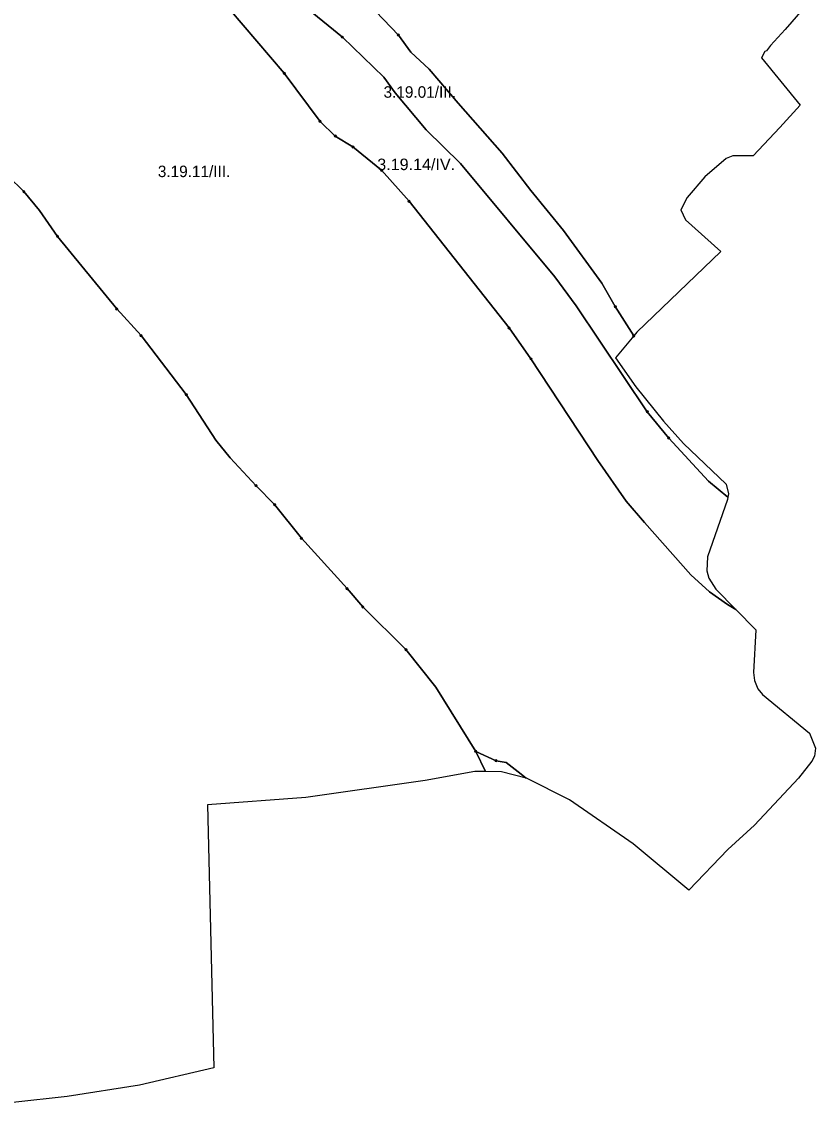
# Model space of a CAD drawing. Extents: x -650455 to -642254, y -1075222 to -1066610.
# Drawn here: x -644416 to -643724, y -1073642 to -1072701 of the extents above; entities that cross this region are included whole.
import ezdxf
from ezdxf.enums import TextEntityAlignment as Align

# ---------------------------------------------------------------- set-up
doc = ezdxf.new("R2010")
doc.units = 0
doc.header["$LTSCALE"] = 4
doc.header["$PDMODE"] = 32
doc.header["$PDSIZE"] = 2
for name, color, linetype, lineweight in [('1', 7, 'Continuous', 25), ('11', 7, 'Continuous', 13), ('12', 7, 'Continuous', 13), ('13', 7, 'Continuous', 13), ('14', 7, 'Continuous', 13)]:
    doc.layers.add(name, color=color, linetype=linetype, lineweight=lineweight)
doc.layers.add('2', color=7, linetype='Continuous')

msp = doc.modelspace()

# ---------------------------------------------------------------- linework, layer by layer
at = {"layer": '1'}
for points in [[(-644133.59, -1072663.941), (-644087.515, -1072712.377), (-644076.499, -1072727.239), (-644060.762, -1072741.927), (-644035.408, -1072771.653), (-643997.027, -1072815.367), (-643971.935, -1072847.715), (-643943.434, -1072882.512), (-643910.123, -1072928.499), (-643898.495, -1072948.957)], [(-643734.991, -1072689.776), (-643750.231, -1072707.416), (-643763.214, -1072721.526), (-643766.742, -1072726.043), (-643768.011, -1072726.748), (-643770.864, -1072732.304), (-643737.297, -1072773.436), (-643755.036, -1072793.028), (-643778.183, -1072817.707), (-643795.921, -1072817.707), (-643801.762, -1072819.98), (-643820.366, -1072835.782), (-643835.725, -1072853.968), (-643841.349, -1072864.684), (-643837.239, -1072873.344), (-643806.535, -1072901.023), (-643879.504, -1072971.156), (-643882.299, -1072974.5), (-643898.495, -1072948.957), (-643910.123, -1072928.499), (-643943.434, -1072882.512), (-643971.935, -1072847.715), (-643997.027, -1072815.367), (-644035.408, -1072771.653), (-644060.762, -1072741.927), (-644076.499, -1072727.239), (-644087.515, -1072712.377), (-644133.59, -1072663.941)], [(-644234.796, -1072689.872), (-644186.973, -1072745.651), (-644155.761, -1072787.617), (-644142.471, -1072800.381), (-644127.172, -1072809.824), (-644102.167, -1072830.107), (-644078.124, -1072857.21), (-643990.959, -1072967.544), (-643971.987, -1072994.472), (-643913.497, -1073082.949), (-643888.93, -1073118.445), (-643872.93, -1073137.155), (-643832.539, -1073182.792), (-643816.189, -1073197.48), (-643800.627, -1073208.496), (-643793.212, -1073213.013), (-643775.773, -1073230.523), (-643778.031, -1073267.918), (-643777.184, -1073274.69), (-643774.079, -1073282.028), (-643769.987, -1073286.968), (-643729.064, -1073320.694)], [(-644165.902, -1072690.047), (-644136.264, -1072714.177), (-644100.069, -1072749.148), (-644090.364, -1072762.787), (-644063.262, -1072794.961), (-644033.274, -1072824.162), (-643951.179, -1072922.956), (-643932.382, -1072948.31), (-643870.57, -1073040.634), (-643851.773, -1073063.54), (-643817.151, -1073100.96), (-643800.254, -1073115.142), (-643800.608, -1073117.208), (-643818.106, -1073166.881), (-643818.53, -1073179.298), (-643816.837, -1073185.507), (-643810.91, -1073195.243), (-643793.212, -1073213.013), (-643800.627, -1073208.496), (-643816.189, -1073197.48), (-643832.539, -1073182.792), (-643872.93, -1073137.155), (-643888.93, -1073118.445), (-643913.497, -1073082.949), (-643971.987, -1072994.472), (-643990.959, -1072967.544), (-644078.124, -1072857.21), (-644102.167, -1072830.107), (-644127.172, -1072809.824), (-644142.471, -1072800.381), (-644155.761, -1072787.617), (-644186.973, -1072745.651), (-644234.796, -1072689.872)], [(-643799.762, -1073112.269), (-643800.254, -1073115.142), (-643817.151, -1073100.96), (-643851.773, -1073063.54), (-643870.57, -1073040.634), (-643932.382, -1072948.31), (-643951.179, -1072922.956), (-644033.274, -1072824.162), (-644063.262, -1072794.961), (-644090.364, -1072762.787), (-644100.069, -1072749.148), (-644136.264, -1072714.177), (-644165.902, -1072690.047)], [(-644427.764, -1072835.165), (-644413.997, -1072848.687), (-644400.183, -1072865.124), (-644384.621, -1072887.855), (-644332.951, -1072950.978), (-644311.793, -1072974.234), (-644272.363, -1073025.642), (-644246.747, -1073065.334), (-644234.157, -1073080.721), (-644211.513, -1073105.026), (-644195.427, -1073121.463), (-644172.083, -1073150.839), (-644132.216, -1073194.728), (-644118.49, -1073210.64), (-644080.896, -1073247.884), (-644054.929, -1073280.582), (-644020.045, -1073336.536), (-644011.677, -1073354.192), (-644020.886, -1073354.137), (-644064.067, -1073362.039), (-644168.209, -1073376.856), (-644253.864, -1073383.206), (-644248.437, -1073612.322), (-644313.273, -1073627.474), (-644376.209, -1073637.35), (-644423.623, -1073642.431)], [(-643729.064, -1073320.694), (-643723.984, -1073333.675), (-643724.69, -1073340.59), (-643726.947, -1073344.965), (-643738.66, -1073359.782), (-643777.043, -1073400.846), (-643800.326, -1073422.013), (-643834.173, -1073457.614), (-643882.878, -1073417.215), (-643938.194, -1073378.691), (-643975.73, -1073359.923), (-643976.242, -1073359.79), (-643983.062, -1073354.416), (-643993.414, -1073346.315), (-644002.385, -1073344.755), (-644020.045, -1073336.536), (-644054.929, -1073280.582), (-644080.896, -1073247.884), (-644118.49, -1073210.64), (-644132.216, -1073194.728), (-644172.083, -1073150.839), (-644195.427, -1073121.463), (-644211.513, -1073105.026), (-644234.157, -1073080.721), (-644246.747, -1073065.334), (-644272.363, -1073025.642), (-644311.793, -1072974.234), (-644332.951, -1072950.978), (-644384.621, -1072887.855), (-644400.183, -1072865.124), (-644413.997, -1072848.687), (-644427.764, -1072835.165)], [(-643898.495, -1072948.957), (-643882.299, -1072974.5), (-643898.324, -1072993.671), (-643880.62, -1073018.853), (-643856.489, -1073048.91), (-643838.991, -1073068.243), (-643801.737, -1073103.803), (-643799.762, -1073112.269)]]:
    msp.add_lwpolyline(points, dxfattribs=at)
msp.add_lwpolyline([(-643983.062, -1073354.416), (-643976.242, -1073359.79), (-643997.462, -1073354.278), (-644011.677, -1073354.192), (-644020.045, -1073336.536), (-644002.385, -1073344.755), (-643993.414, -1073346.315)], close=True, dxfattribs=at)
at = {"layer": '11'}
for points in [[(-644133.59, -1072663.941), (-644087.515, -1072712.377), (-644076.499, -1072727.239), (-644060.762, -1072741.927), (-644035.408, -1072771.653)], [(-643882.299, -1072974.5), (-643879.504, -1072971.156), (-643806.535, -1072901.023), (-643837.239, -1072873.344), (-643841.349, -1072864.684), (-643835.725, -1072853.968), (-643820.366, -1072835.782), (-643801.762, -1072819.98), (-643795.921, -1072817.707), (-643778.183, -1072817.707), (-643755.036, -1072793.028), (-643737.297, -1072773.436), (-643770.864, -1072732.304), (-643768.011, -1072726.748), (-643766.742, -1072726.043), (-643763.214, -1072721.526), (-643750.231, -1072707.416), (-643734.991, -1072689.776)], [(-644035.408, -1072771.653), (-643997.027, -1072815.367), (-643971.935, -1072847.715), (-643943.434, -1072882.512), (-643910.123, -1072928.499), (-643898.495, -1072948.957), (-643882.299, -1072974.5)]]:
    msp.add_lwpolyline(points, dxfattribs=at)
msp.add_point((-643882.299, -1072974.5), dxfattribs=at)
at = {"layer": '12'}
for points in [[(-644332.951, -1072950.978), (-644384.621, -1072887.855), (-644400.183, -1072865.124), (-644413.997, -1072848.687), (-644427.764, -1072835.165)], [(-644211.513, -1073105.026), (-644234.157, -1073080.721), (-644246.747, -1073065.334), (-644272.363, -1073025.642), (-644311.793, -1072974.234), (-644332.951, -1072950.978)], [(-644132.216, -1073194.728), (-644172.083, -1073150.839), (-644195.427, -1073121.463), (-644211.513, -1073105.026)], [(-644423.623, -1073642.431), (-644376.209, -1073637.35), (-644313.273, -1073627.474), (-644248.437, -1073612.322), (-644253.864, -1073383.206), (-644168.209, -1073376.856), (-644064.067, -1073362.039), (-644020.886, -1073354.137), (-644011.677, -1073354.192), (-644020.045, -1073336.536), (-644054.929, -1073280.582), (-644080.896, -1073247.884), (-644118.49, -1073210.64), (-644132.216, -1073194.728)]]:
    msp.add_lwpolyline(points, dxfattribs=at)
for p in [(-644332.951, -1072950.978), (-644211.513, -1073105.026), (-644132.216, -1073194.728)]:
    msp.add_point(p, dxfattribs=at)
at = {"layer": '13'}
for p, q in [((-644155.761, -1072787.617), (-644186.973, -1072745.651)), ((-644142.471, -1072800.381), (-644155.761, -1072787.617)), ((-644311.793, -1072974.234), (-644272.363, -1073025.642)), ((-644195.427, -1073121.463), (-644172.083, -1073150.839)), ((-644172.083, -1073150.839), (-644132.216, -1073194.728)), ((-644132.216, -1073194.728), (-644118.49, -1073210.64)), ((-644118.49, -1073210.64), (-644080.896, -1073247.884)), ((-644020.045, -1073336.536), (-644002.385, -1073344.755))]:
    msp.add_line(p, q, dxfattribs=at)
for points in [[(-644087.515, -1072712.377), (-644133.59, -1072663.941), (-644141.983, -1072654.499), (-644148.278, -1072649.253), (-644177.392, -1072620.927), (-644195.402, -1072601.518), (-644209.565, -1072583.682), (-644221.018, -1072567.071), (-644234.482, -1072548.536), (-644249.695, -1072522.483), (-644262.896, -1072504.647), (-644270.415, -1072497.128), (-644262.896, -1072532.799), (-644259.8, -1072552.61), (-644255.953, -1072567.997), (-644245.025, -1072592.302), (-644236.282, -1072610.662), (-644215.824, -1072635.667), (-644184.262, -1072673.086), (-644165.902, -1072690.047), (-644136.264, -1072714.177)], [(-644186.973, -1072745.651), (-644234.796, -1072689.872), (-644258.227, -1072667.141), (-644304.476, -1072617.307)], [(-644136.264, -1072714.177), (-644100.069, -1072749.148), (-644090.364, -1072762.787), (-644063.262, -1072794.961), (-644033.274, -1072824.162), (-643951.179, -1072922.956), (-643932.382, -1072948.31), (-643870.57, -1073040.634), (-643851.773, -1073063.54)], [(-643898.495, -1072948.957), (-643910.123, -1072928.499), (-643943.434, -1072882.512), (-643971.935, -1072847.715), (-643997.027, -1072815.367), (-644035.408, -1072771.653), (-644060.762, -1072741.927), (-644076.499, -1072727.239), (-644087.515, -1072712.377)], [(-644102.167, -1072830.107), (-644127.172, -1072809.824), (-644142.471, -1072800.381)], [(-644424.966, -1072822.225), (-644427.764, -1072835.165), (-644413.997, -1072848.687)], [(-643971.987, -1072994.472), (-643990.959, -1072967.544), (-644078.124, -1072857.21), (-644102.167, -1072830.107)], [(-644413.997, -1072848.687), (-644400.183, -1072865.124), (-644384.621, -1072887.855)], [(-644384.621, -1072887.855), (-644332.951, -1072950.978), (-644311.793, -1072974.234)], [(-643851.773, -1073063.54), (-643817.151, -1073100.96), (-643800.254, -1073115.142), (-643799.762, -1073112.269), (-643801.737, -1073103.803), (-643838.991, -1073068.243), (-643856.489, -1073048.91), (-643880.62, -1073018.853), (-643898.324, -1072993.671), (-643882.299, -1072974.5), (-643898.495, -1072948.957)], [(-644002.385, -1073344.755), (-643993.414, -1073346.315), (-643983.062, -1073354.416), (-643976.242, -1073359.79), (-643975.73, -1073359.923), (-643938.194, -1073378.691), (-643882.878, -1073417.215), (-643834.173, -1073457.614), (-643800.326, -1073422.013), (-643777.043, -1073400.846), (-643738.66, -1073359.782), (-643726.947, -1073344.965), (-643724.69, -1073340.59), (-643723.984, -1073333.675), (-643729.064, -1073320.694), (-643769.987, -1073286.968), (-643774.079, -1073282.028), (-643777.184, -1073274.69), (-643778.031, -1073267.918), (-643775.773, -1073230.523), (-643793.212, -1073213.013), (-643800.627, -1073208.496), (-643816.189, -1073197.48), (-643832.539, -1073182.792), (-643872.93, -1073137.155), (-643888.93, -1073118.445), (-643913.497, -1073082.949), (-643971.987, -1072994.472)], [(-644272.363, -1073025.642), (-644246.747, -1073065.334), (-644234.157, -1073080.721), (-644211.513, -1073105.026), (-644195.427, -1073121.463)], [(-644080.896, -1073247.884), (-644054.929, -1073280.582), (-644020.045, -1073336.536)]]:
    msp.add_lwpolyline(points, dxfattribs=at)
for p in [(-644136.264, -1072714.177), (-644087.515, -1072712.377), (-644186.973, -1072745.651), (-644155.761, -1072787.617), (-644142.471, -1072800.381), (-644102.167, -1072830.107), (-644413.997, -1072848.687), (-644384.621, -1072887.855), (-643898.495, -1072948.957), (-644311.793, -1072974.234), (-643971.987, -1072994.472), (-644272.363, -1073025.642), (-643851.773, -1073063.54), (-644195.427, -1073121.463), (-644172.083, -1073150.839), (-644132.216, -1073194.728), (-644118.49, -1073210.64), (-644080.896, -1073247.884), (-644020.045, -1073336.536), (-644002.385, -1073344.755)]:
    msp.add_point(p, dxfattribs=at)
at = {"layer": '14'}
for p, q in [((-644078.124, -1072857.21), (-643990.959, -1072967.544)), ((-643990.959, -1072967.544), (-643971.987, -1072994.472))]:
    msp.add_line(p, q, dxfattribs=at)
for points in [[(-644258.227, -1072667.141), (-644234.796, -1072689.872), (-644186.973, -1072745.651), (-644155.761, -1072787.617), (-644142.471, -1072800.381), (-644127.172, -1072809.824)], [(-643870.57, -1073040.634), (-643932.382, -1072948.31), (-643951.179, -1072922.956), (-644033.274, -1072824.162), (-644063.262, -1072794.961), (-644090.364, -1072762.787), (-644100.069, -1072749.148), (-644136.264, -1072714.177), (-644165.902, -1072690.047)], [(-644127.172, -1072809.824), (-644102.167, -1072830.107), (-644078.124, -1072857.21)], [(-643971.987, -1072994.472), (-643913.497, -1073082.949), (-643888.93, -1073118.445), (-643872.93, -1073137.155), (-643832.539, -1073182.792), (-643816.189, -1073197.48), (-643800.627, -1073208.496), (-643793.212, -1073213.013), (-643810.91, -1073195.243), (-643816.837, -1073185.507), (-643818.53, -1073179.298), (-643818.106, -1073166.881), (-643800.608, -1073117.208), (-643800.254, -1073115.142), (-643817.151, -1073100.96), (-643851.773, -1073063.54), (-643870.57, -1073040.634)]]:
    msp.add_lwpolyline(points, dxfattribs=at)
for p in [(-644127.172, -1072809.824), (-644078.124, -1072857.21), (-643990.959, -1072967.544), (-643971.987, -1072994.472), (-643870.57, -1073040.634)]:
    msp.add_point(p, dxfattribs=at)

# ---------------------------------------------------------------- texts
at = {"layer": '2'}
for s, p in [('3.19.01/III.', (-644068.816, -1072766.968)), ('3.19.11/III.', (-644265.576, -1072836.138))]:
    msp.add_text(s, height=10, dxfattribs=at).set_placement(p, align=Align.CENTER)
at = {"layer": '2', "width": 1.05}
msp.add_text('3.19.14/IV.', height=10, dxfattribs=at).set_placement((-644071.954, -1072830.022), align=Align.CENTER)

doc.saveas('drawing.dxf')
